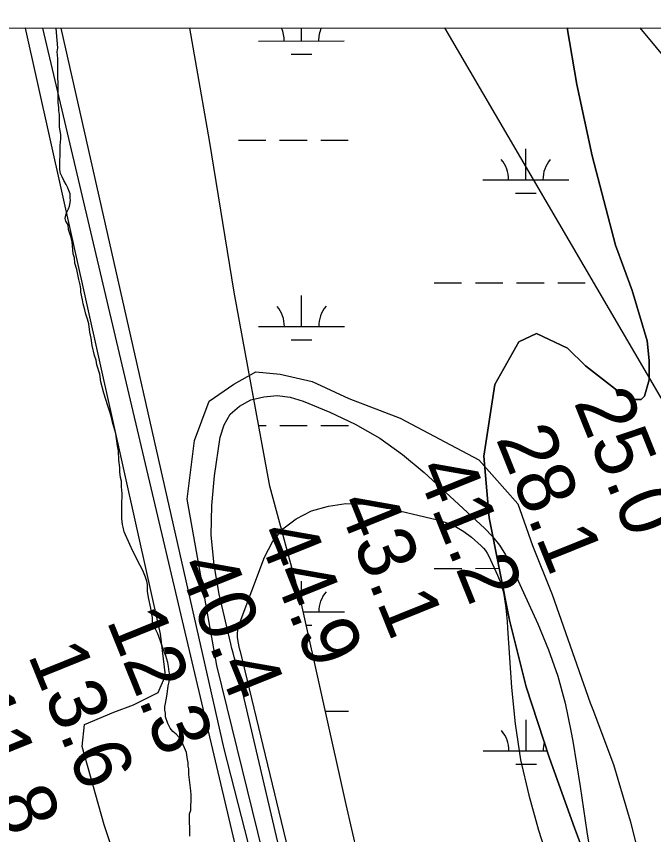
# Model space of a CAD drawing. Extents: x 3279314 to 3317160, y 734079 to 759431.
# Drawn here: x 3287854 to 3288596, y 756704 to 757657 of the extents above; entities that cross this region are included whole.
import ezdxf

# ---------------------------------------------------------------- set-up
doc = ezdxf.new("R2010")
doc.units = 0
for name, color, linetype in [('V-GRID-FRAM', 7, 'Continuous'), ('V-RIVR-RANG', 7, 'Continuous'), ('V-SITE-VEGE', 7, 'Continuous'), ('V-TOPO-DPTH', 7, 'Continuous'), ('V-TOPO-MAJR', 7, 'Continuous'), ('V-TOPO-MINR', 7, 'Continuous'), ('V-TOPO-SHOR', 7, 'Continuous'), ('V-WETL-SWMP', 7, 'Continuous')]:
    doc.layers.add(name, color=color, linetype=linetype)

msp = doc.modelspace()

# ---------------------------------------------------------------- linework, layer by layer
at = {"layer": 'V-GRID-FRAM'}
msp.add_lwpolyline([(3283455.67, 757641.37), (3314923.72, 757657.39), (3314940.91, 739471.92), (3283456.99, 739455.89), (3283455.67, 757641.37)], dxfattribs=at)
at = {"layer": 'V-SITE-VEGE'}
for p, q in [((3287900.28, 757643.63), (3288495.68, 757643.94)), ((3287900.76, 757638.77), (3287900.28, 757643.63)), ((3287902.19, 757620.66), (3287900.76, 757638.77)), ((3288495.68, 757643.94), (3288507.05, 757578.05)), ((3287901.58, 757616.13), (3287902.19, 757620.66)), ((3287902.29, 757608.37), (3287901.58, 757616.13)), ((3287902.67, 757557.23), (3287902.29, 757608.37)), ((3288507.05, 757578.05), (3288524.76, 757494.79)), ((3287903.36, 757550.77), (3287902.67, 757557.23)), ((3287903.39, 757547.53), (3287903.36, 757550.77)), ((3287904.07, 757543.01), (3287903.39, 757547.53)), ((3287904.18, 757528.12), (3287904.07, 757543.01)), ((3287905.54, 757519.71), (3287904.18, 757528.12)), ((3287904.98, 757506.76), (3287905.58, 757514.54)), ((3287905.58, 757514.54), (3287905.54, 757519.71)), ((3287905.06, 757496.41), (3287904.98, 757506.76)), ((3287904.48, 757488.64), (3287905.06, 757496.41)), ((3288524.76, 757494.79), (3288552.1, 757390.75)), ((3287904.55, 757478.93), (3287904.48, 757488.64)), ((3287905.23, 757474.4), (3287904.55, 757478.93)), ((3287907.2, 757470.53), (3287905.23, 757474.4)), ((3287909.18, 757466.02), (3287907.2, 757470.53)), ((3287911.8, 757461.51), (3287909.18, 757466.02)), ((3287913.77, 757457.64), (3287911.8, 757461.51)), ((3287915.09, 757454.41), (3287913.77, 757457.64)), ((3287916.41, 757450.54), (3287915.09, 757454.41)), ((3287916.45, 757446.01), (3287916.41, 757450.54)), ((3287917.12, 757442.77), (3287916.45, 757446.01)), ((3287914.6, 757433.05), (3287915.87, 757436.29)), ((3287915.87, 757436.29), (3287917.12, 757442.77)), ((3287911.42, 757425.9), (3287912.69, 757429.15)), ((3287912.69, 757429.15), (3287914.6, 757433.05)), ((3287910.8, 757422.02), (3287911.42, 757425.9)), ((3287911.47, 757418.78), (3287910.8, 757422.02)), ((3287914.09, 757414.27), (3287911.47, 757418.78)), ((3287914.78, 757409.1), (3287914.09, 757414.27)), ((3287917.43, 757400.7), (3287914.78, 757409.1)), ((3287918.77, 757394.89), (3287917.43, 757400.7)), ((3287920.17, 757380.66), (3287918.77, 757394.89)), ((3288552.1, 757390.75), (3288571.47, 757337.82)), ((3287921.5, 757376.14), (3287920.17, 757380.66)), ((3287922.2, 757369.67), (3287921.5, 757376.14)), ((3287924.19, 757362.56), (3287922.2, 757369.67)), ((3287926.87, 757350.94), (3287924.19, 757362.56)), ((3287928.21, 757344.47), (3287926.87, 757350.94)), ((3287928.89, 757339.95), (3287928.21, 757344.47)), ((3287928.92, 757336.06), (3287928.89, 757339.95)), ((3287930.93, 757327.02), (3287928.92, 757336.06)), ((3288571.47, 757337.82), (3288588.98, 757279.2)), ((3287931.61, 757322.49), (3287930.93, 757327.02)), ((3287933.61, 757315.39), (3287931.61, 757322.49)), ((3287934.94, 757310.22), (3287933.61, 757315.39)), ((3287936.93, 757304.41), (3287934.94, 757310.22)), ((3287938.26, 757299.24), (3287936.93, 757304.41)), ((3287939.62, 757289.54), (3287938.26, 757299.24)), ((3287940.97, 757282.43), (3287939.62, 757289.54)), ((3288460.03, 757287.68), (3288439.25, 757278.04)), ((3288496.17, 757270.9), (3288460.03, 757287.68)), ((3287942.33, 757274.02), (3287940.97, 757282.43)), ((3287945.01, 757262.39), (3287942.33, 757274.02)), ((3288439.25, 757278.04), (3288411.21, 757228.54)), ((3288588.98, 757279.2), (3288591.06, 757256.47)), ((3288517.18, 757250.21), (3288496.17, 757270.9)), ((3287946.99, 757256.58), (3287945.01, 757262.39)), ((3287947.68, 757251.41), (3287946.99, 757256.58)), ((3288591.06, 757256.47), (3288591.23, 757233.73)), ((3287951, 757240.43), (3287947.68, 757251.41)), ((3288555.33, 757220.19), (3288517.18, 757250.21)), ((3287952.36, 757231.38), (3287951, 757240.43)), ((3287955.69, 757218.46), (3287952.36, 757231.38)), ((3288411.21, 757228.54), (3288398.59, 757145.04)), ((3288591.23, 757233.73), (3288585.69, 757214.73)), ((3287960.33, 757203.61), (3287955.69, 757218.46)), ((3288572.46, 757210.84), (3288555.33, 757220.19)), ((3288581.93, 757210.91), (3288572.46, 757210.84)), ((3288585.69, 757214.73), (3288581.93, 757210.91)), ((3287962.32, 757197.79), (3287960.33, 757203.61)), ((3287964.31, 757191.34), (3287962.32, 757197.79)), ((3287966.31, 757182.94), (3287964.31, 757191.34)), ((3287969.64, 757171.31), (3287966.31, 757182.94)), ((3287971.69, 757157.09), (3287969.64, 757171.31)), ((3287973.02, 757151.27), (3287971.69, 757157.09)), ((3287973.11, 757140.27), (3287973.02, 757151.27)), ((3287974.46, 757131.86), (3287973.11, 757140.27)), ((3288398.59, 757145.04), (3288404.83, 757073.06)), ((3287974.5, 757126.69), (3287974.46, 757131.86)), ((3287975.2, 757120.22), (3287974.5, 757126.69)), ((3287976.53, 757115.7), (3287975.2, 757120.22)), ((3287976.57, 757109.22), (3287976.53, 757115.7)), ((3287977.28, 757101.46), (3287976.57, 757109.22)), ((3287976.71, 757090.45), (3287977.3, 757098.23)), ((3287977.3, 757098.23), (3287977.28, 757101.46)), ((3287976.85, 757072.33), (3287976.71, 757090.45)), ((3287977.55, 757065.22), (3287976.85, 757072.33)), ((3287978.22, 757061.99), (3287977.55, 757065.22)), ((3288404.83, 757073.06), (3288428.51, 756953.83)), ((3287979.56, 757056.82), (3287978.22, 757061.99)), ((3287986.14, 757041.98), (3287979.56, 757056.82)), ((3287989.43, 757034.24), (3287986.14, 757041.98)), ((3287997.97, 757017.47), (3287989.43, 757034.24)), ((3288001.25, 757011.67), (3287997.97, 757017.47)), ((3288004.55, 757003.93), (3288001.25, 757011.67)), ((3288005.88, 756999.41), (3288004.55, 757003.93)), ((3288006.55, 756995.53), (3288005.88, 756999.41)), ((3288006.61, 756987.76), (3288006.55, 756995.53)), ((3288007.96, 756980), (3288006.61, 756987.76)), ((3288010.65, 756967.73), (3288007.96, 756980)), ((3288011.34, 756961.91), (3288010.65, 756967.73)), ((3288012.67, 756956.74), (3288011.34, 756961.91)), ((3288012.71, 756950.91), (3288012.67, 756956.74)), ((3288016.01, 756943.17), (3288012.71, 756950.91)), ((3288428.51, 756953.83), (3288448.06, 756876.27)), ((3288018.64, 756938.01), (3288016.01, 756943.17)), ((3288019.95, 756934.78), (3288018.64, 756938.01)), ((3288025.25, 756919.29), (3288019.95, 756934.78)), ((3288027.89, 756912.19), (3288025.25, 756919.29)), ((3288030.54, 756904.44), (3288027.89, 756912.19)), ((3288031.22, 756899.92), (3288030.54, 756904.44)), ((3288031.91, 756893.45), (3288031.22, 756899.92)), ((3288033.24, 756888.93), (3288031.91, 756893.45)), ((3288032, 756881.8), (3288033.24, 756888.93)), ((3288029.52, 756867.54), (3288030.74, 756877.26)), ((3288030.74, 756877.26), (3288032, 756881.8)), ((3288448.06, 756876.27), (3288475.25, 756793.08)), ((3288028.27, 756861.06), (3288029.52, 756867.54)), ((3288027.04, 756853.28), (3288027.66, 756856.52)), ((3288027.66, 756856.52), (3288028.27, 756861.06)), ((3288027.07, 756848.75), (3288027.04, 756853.28)), ((3288027.74, 756845.52), (3288027.07, 756848.75)), ((3288027.77, 756840.99), (3288027.74, 756845.52)), ((3288030.42, 756833.24), (3288027.77, 756840.99)), ((3288033.05, 756828.08), (3288030.42, 756833.24)), ((3288036.32, 756824.22), (3288033.05, 756828.08)), ((3288040.22, 756821.02), (3288036.32, 756824.22)), ((3288044.14, 756816.51), (3288040.22, 756821.02)), ((3288046.1, 756813.94), (3288044.14, 756816.51)), ((3288052.03, 756799.75), (3288046.1, 756813.94)), ((3288053.39, 756791.34), (3288052.03, 756799.75)), ((3288054.06, 756788.11), (3288053.39, 756791.34)), ((3288054.1, 756783.58), (3288054.06, 756788.11)), ((3288475.25, 756793.08), (3288504.31, 756711.8)), ((3288054.77, 756780.35), (3288054.1, 756783.58)), ((3288054.82, 756773.88), (3288054.77, 756780.35)), ((3288056.87, 756758.35), (3288054.82, 756773.88)), ((3288057.58, 756750.59), (3288056.87, 756758.35)), ((3288057.64, 756742.83), (3288057.58, 756750.59)), ((3288057.03, 756737.64), (3288057.64, 756742.83)), ((3288055.81, 756727.93), (3288057.07, 756732.46)), ((3288057.07, 756732.46), (3288057.03, 756737.64)), ((3288056, 756702.04), (3288055.81, 756727.93)), ((3288504.31, 756711.8), (3288548.83, 756592.74))]:
    msp.add_line(p, q, dxfattribs=at)
at = {"layer": 'V-TOPO-DPTH'}
msp.add_lwpolyline([(3288353.31, 755833.79), (3288113.44, 756204.61), (3288013.39, 756544.11), (3287956.24, 756715.29), (3287930.51, 756806.58), (3287933.35, 756832.26), (3287967.59, 756846.55), (3287990.41, 756855.12), (3288018.94, 756869.4), (3288027.49, 756889.38), (3288021.75, 756937.88), (3287864.55, 757643.62), (3287417.22, 757643.39)], dxfattribs=at)
at = {"layer": 'V-TOPO-MAJR'}
for p, q in [((3288649.82, 757136.27), (3288353.18, 757643.86)), ((3288522.49, 756857.62), (3288525.76, 756849.81)), ((3288525.76, 756849.81), (3288549.48, 756785.53)), ((3288549.48, 756785.53), (3288569.04, 756719.86)), ((3288569.04, 756719.86), (3288585.81, 756653.27))]:
    msp.add_line(p, q, dxfattribs=at)
msp.add_lwpolyline([(3288344.69, 755956.48), (3288236.09, 756295.98), (3288087.4, 756900.82), (3288053.06, 757094.84), (3288061.59, 757163.32), (3288078.68, 757208.99), (3288107.21, 757228.97), (3288132.88, 757243.25), (3288161.42, 757240.42), (3288198.52, 757231.87), (3288241.33, 757211.92), (3288301.26, 757189.13), (3288392.59, 757140.66), (3288438.27, 757089.33), (3288455.42, 757040.83), (3288478.27, 756983.77), (3288522.49, 756857.62)], dxfattribs=at)
at = {"layer": 'V-TOPO-MINR'}
msp.add_line((3288878.8, 757283.73), (3288580.67, 757643.98), dxfattribs=at)
for points in [[(3288353.31, 755833.79), (3288113.44, 756204.61), (3288013.39, 756544.11), (3287956.24, 756715.29), (3287930.51, 756806.58), (3287933.35, 756832.26), (3287967.59, 756846.55), (3287990.41, 756855.12), (3288018.94, 756869.4), (3288027.49, 756889.38), (3288021.75, 756937.88), (3287864.55, 757643.62)], [(3289451.03, 754529.25), (3289008.73, 754718.44), (3288823.21, 754813.94), (3288594.88, 754943.65), (3288534.93, 754990.7), (3288480.68, 755054.88), (3288370.76, 755191.78), (3288350.74, 755268.81), (3288387.79, 755360.14), (3288424.85, 755440.06), (3288444.8, 755482.87), (3288456.18, 755539.94), (3288459.02, 755579.89), (3288464.69, 755642.67), (3288450.4, 755685.46), (3288441.83, 755702.58), (3288430.4, 755736.81), (3288413.26, 755788.16), (3288333.3, 755902.26), (3288261.9, 756036.33), (3288196.13, 756315.93), (3288116.06, 756661.15), (3287884.75, 757643.63)], [(3289465.04, 754551.51), (3289013.01, 754727.01), (3288607.71, 754952.22), (3288559.19, 754986.43), (3288502.08, 755072.01), (3288502.02, 755180.44), (3288559.04, 755280.33), (3288604.64, 755374.52), (3288610.3, 755471.54), (3288584.58, 755557.13), (3288538.87, 755665.53), (3288473.2, 755748.25), (3288413.23, 755828.11), (3288353.28, 755893.71), (3288233.26, 756241.76), (3288164.63, 756535.63), (3288096.01, 756803.81), (3287906.19, 757643.64)], [(3288249.76, 756305.62), (3288109.3, 756905.47), (3288107.78, 756910.61), (3288106.33, 756915.76), (3288104.99, 756920.95), (3288103.73, 756926.15), (3288090.26, 756984.07), (3288084.32, 757018.33), (3288080.97, 757052.7), (3288081.52, 757087.22), (3288084.65, 757121.85), (3288091.34, 757167.01), (3288096.04, 757181.34), (3288103.14, 757193.71), (3288113.85, 757203.12), (3288126.97, 757210.57), (3288142.34, 757214.21), (3288157.66, 757215.57), (3288172.9, 757213.5), (3288188.08, 757209.14), (3288219.1, 757196.27), (3288248.79, 757182.05), (3288277.23, 757165.89), (3288303.8, 757146.8), (3288329.13, 757125.77), (3288399.27, 757060.9), (3288408.5, 757051.28), (3288416.87, 757041.05), (3288423.97, 757029.9), (3288430.22, 757018.13), (3288461.5, 756949.61), (3288473.94, 756919.32), (3288484.77, 756888.54), (3288493.2, 756857.01), (3288500.03, 756824.99), (3288502.14, 756812.8), (3288506.56, 756786.47), (3288510.79, 756760.12), (3288514.74, 756733.72), (3288518.5, 756707.3), (3288522.85, 756681.02)], [(3288260.91, 756311.64), (3288115, 756917.38), (3288114.73, 756918.23), (3288114.47, 756919.08), (3288114.25, 756919.94), (3288114.04, 756920.81), (3288112.22, 756929.04), (3288111.58, 756934), (3288111.49, 756938.92), (3288112.26, 756943.77), (3288113.59, 756948.59), (3288142.94, 757027.16), (3288152.46, 757044.91), (3288164.35, 757060.26), (3288179.83, 757071.98), (3288197.69, 757081.3), (3288217.75, 757086.61), (3288237.95, 757089.57), (3288258.36, 757089), (3288278.9, 757086.07), (3288344.71, 757070.73), (3288355.43, 757067.36), (3288365.64, 757063.03), (3288375.11, 757057.23), (3288384.08, 757050.47), (3288395.44, 757040.47), (3288398.13, 757037.78), (3288400.57, 757034.91), (3288402.62, 757031.74), (3288404.41, 757028.39), (3288414.55, 757006.19), (3288417.51, 756998.85), (3288420.01, 756991.39), (3288421.82, 756983.73), (3288423.18, 756975.95), (3288424.12, 756968.05), (3288424.96, 756960.15), (3288425.65, 756952.23), (3288426.25, 756944.3), (3288430.77, 756875.14), (3288435.1, 756832.92), (3288441.47, 756791.09), (3288450.88, 756749.84), (3288462.34, 756708.97), (3288535.11, 756481.81)]]:
    msp.add_lwpolyline(points, dxfattribs=at)
at = {"layer": 'V-TOPO-SHOR'}
msp.add_lwpolyline([(3288548.83, 756592.74), (3288504.31, 756711.8), (3288475.25, 756793.08), (3288448.06, 756876.27), (3288428.51, 756953.83), (3288404.83, 757073.06), (3288398.59, 757145.04), (3288411.21, 757228.54), (3288439.25, 757278.04), (3288460.03, 757287.68), (3288496.17, 757270.9), (3288517.18, 757250.21), (3288555.33, 757220.18), (3288572.46, 757210.84), (3288581.93, 757210.91), (3288585.69, 757214.73), (3288591.23, 757233.73), (3288591.06, 757256.48), (3288588.98, 757279.2), (3288571.47, 757337.83), (3288552.1, 757390.75), (3288524.76, 757494.79), (3288507.05, 757578.05), (3288495.68, 757643.94)], dxfattribs=at)
at = {"layer": 'V-WETL-SWMP'}
for p, q in [((3288055.95, 757643.71), (3288495.68, 757643.94)), ((3288055.95, 757643.71), (3288495.68, 757643.94)), ((3288079.02, 757512.65), (3288055.95, 757643.71)), ((3288079.02, 757512.65), (3288055.95, 757643.71)), ((3288186, 757628.68), (3288185.99, 757643.78)), ((3288495.68, 757643.94), (3288507.05, 757578.05)), ((3288495.68, 757643.94), (3288507.05, 757578.05)), ((3288136, 757628.65), (3288236, 757628.7)), ((3288174, 757613.24), (3288198, 757613.25)), ((3288507.05, 757578.05), (3288524.76, 757494.79)), ((3288507.05, 757578.05), (3288524.76, 757494.79)), ((3288107.5, 757335.9), (3288079.02, 757512.65)), ((3288107.5, 757335.9), (3288079.02, 757512.65)), ((3288112.65, 757513.21), (3288144.65, 757513.22)), ((3288160.65, 757513.23), (3288192.65, 757513.25)), ((3288208.65, 757513.26), (3288240.65, 757513.27)), ((3288447.51, 757466.95), (3288447.5, 757502.95)), ((3288524.76, 757494.79), (3288552.1, 757390.75)), ((3288524.76, 757494.79), (3288552.1, 757390.75)), ((3288397.51, 757466.92), (3288497.51, 757466.97)), ((3288435.52, 757451.51), (3288459.52, 757451.52)), ((3288552.1, 757390.75), (3288571.47, 757337.83)), ((3288552.1, 757390.75), (3288571.47, 757337.83)), ((3288340.73, 757346.82), (3288372.73, 757346.84)), ((3288388.73, 757346.85), (3288420.73, 757346.86)), ((3288436.73, 757346.87), (3288468.73, 757346.89)), ((3288484.73, 757346.9), (3288516.73, 757346.91)), ((3288149.12, 757109.83), (3288107.5, 757335.9)), ((3288149.12, 757109.83), (3288107.5, 757335.9)), ((3288186.17, 757296), (3288186.15, 757332)), ((3288571.47, 757337.83), (3288588.99, 757279.21)), ((3288571.47, 757337.83), (3288588.99, 757279.21)), ((3288136.17, 757295.98), (3288236.17, 757296.03)), ((3288460.03, 757287.68), (3288439.25, 757278.04)), ((3288460.03, 757287.68), (3288439.25, 757278.04)), ((3288496.17, 757270.9), (3288460.03, 757287.68)), ((3288496.17, 757270.9), (3288460.03, 757287.68)), ((3288174.17, 757280.56), (3288198.17, 757280.58)), ((3288439.25, 757278.04), (3288411.21, 757228.54)), ((3288439.25, 757278.04), (3288411.21, 757228.54)), ((3288588.99, 757279.21), (3288591.06, 757256.48)), ((3288588.99, 757279.21), (3288591.06, 757256.48)), ((3288517.18, 757250.22), (3288496.17, 757270.9)), ((3288517.18, 757250.22), (3288496.17, 757270.9)), ((3288591.06, 757256.48), (3288591.23, 757233.73)), ((3288591.06, 757256.48), (3288591.23, 757233.73)), ((3288555.33, 757220.19), (3288517.18, 757250.22)), ((3288555.33, 757220.19), (3288517.18, 757250.22)), ((3288411.21, 757228.54), (3288398.59, 757145.05)), ((3288411.21, 757228.54), (3288398.59, 757145.05)), ((3288591.23, 757233.73), (3288585.7, 757214.74)), ((3288591.23, 757233.73), (3288585.7, 757214.74)), ((3288572.46, 757210.84), (3288555.33, 757220.19)), ((3288572.46, 757210.84), (3288555.33, 757220.19)), ((3288581.93, 757210.92), (3288572.46, 757210.84)), ((3288581.93, 757210.92), (3288572.46, 757210.84)), ((3288585.7, 757214.74), (3288581.93, 757210.92)), ((3288585.7, 757214.74), (3288581.93, 757210.92)), ((3288136.1, 757180.54), (3288144.82, 757180.55)), ((3288160.82, 757180.56), (3288192.82, 757180.57)), ((3288208.82, 757180.58), (3288240.82, 757180.6)), ((3288398.59, 757145.05), (3288404.83, 757073.07)), ((3288398.59, 757145.05), (3288404.83, 757073.07)), ((3288397.68, 757134.25), (3288399.52, 757134.25)), ((3288185.23, 756976.19), (3288149.12, 757109.83)), ((3288185.23, 756976.19), (3288149.12, 757109.83)), ((3288404.83, 757073.07), (3288428.51, 756953.84)), ((3288404.83, 757073.07), (3288428.51, 756953.84)), ((3288340.9, 757014.15), (3288372.9, 757014.16)), ((3288388.9, 757014.17), (3288416.52, 757014.19)), ((3288186.33, 756971.26), (3288186.32, 756999.33)), ((3288238.1, 756739.04), (3288185.23, 756976.19)), ((3288238.1, 756739.04), (3288185.23, 756976.19)), ((3288188.1, 756963.33), (3288236.34, 756963.35)), ((3288428.51, 756953.84), (3288448.06, 756876.28)), ((3288428.51, 756953.84), (3288448.06, 756876.28)), ((3288191.54, 756947.9), (3288198.34, 756947.9)), ((3288448.06, 756876.28), (3288475.25, 756793.09)), ((3288448.06, 756876.28), (3288475.25, 756793.09)), ((3288213.83, 756847.91), (3288240.99, 756847.92)), ((3288447.85, 756801.6), (3288447.84, 756837.6)), ((3288397.85, 756801.57), (3288472.46, 756801.61)), ((3288475.25, 756793.09), (3288504.31, 756711.81)), ((3288475.25, 756793.09), (3288504.31, 756711.81)), ((3288435.86, 756786.16), (3288459.86, 756786.17)), ((3288254.6, 756667.42), (3288238.1, 756739.04)), ((3288254.6, 756667.42), (3288238.1, 756739.04)), ((3288504.31, 756711.81), (3288548.83, 756592.74)), ((3288504.31, 756711.81), (3288548.83, 756592.74))]:
    msp.add_line(p, q, dxfattribs=at)
for centre, start, end in [((3288130.75, 757629.12), 359.25735, 24.55033), ((3288241.24, 757629.18), 155.50801, 180.801), ((3288392.27, 757467.39), 359.25735, 40.80101), ((3288502.76, 757467.45), 139.25734, 180.801), ((3288130.92, 757296.45), 359.25735, 40.80101), ((3288241.41, 757296.5), 139.25734, 180.801), ((3288241.58, 756963.83), 139.25734, 180.801), ((3288392.61, 756802.04), 359.25735, 40.80101), ((3288503.1, 756802.1), 164.24148, 180.801)]:
    msp.add_arc(centre, 35.25, start, end, dxfattribs=at)

# ---------------------------------------------------------------- texts
at = {"layer": 'V-RIVR-RANG'}
for s, rotation, p in [('25.0', 291.93833, (3288502.92, 757207.95)), ('28.1', 291.93833, (3288412.22, 757165.47)), ('41.2', 291.93833, (3288318.66, 757130.09)), ('43.1', 291.93833, (3288226.88, 757090.3)), ('44.9', 291.93833, (3288133.23, 757055.16)), ('40.4', 291.93833, (3288040.66, 757017.33)), ('12.3', 291.99825, (3287958.46, 756953.5)), ('13.6', 291.99825, (3287866.78, 756913.47)), ('11.8', 291.99825, (3287780.44, 756860.23))]:
    msp.add_text(s, height=67, rotation=rotation, dxfattribs=at).set_placement(p)

doc.saveas('drawing.dxf')
